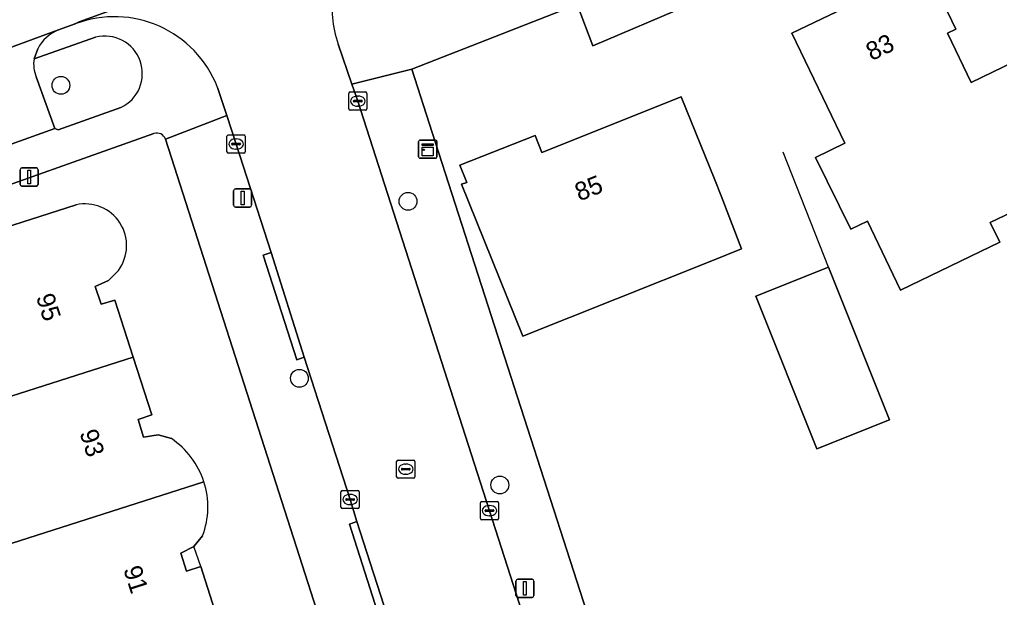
# Model space of a CAD drawing. Extents: x 159499 to 160349, y 382524 to 383273.
# Drawn here: x 159697.8 to 159751.6, y 382905.5 to 382937.3 of the extents above; entities that cross this region are included whole.
import ezdxf

# ---------------------------------------------------------------- set-up
doc = ezdxf.new("R2010")
doc.units = 0
for name, color, linetype in [('IMGEO_Boom', 7, 'Continuous'), ('IMGEO_Erf', 7, 'Continuous'), ('IMGEO_Groenvoorziening', 7, 'Continuous'), ('IMGEO_Kast', 7, 'Continuous'), ('IMGEO_Kolk', 7, 'Continuous'), ('IMGEO_Lichtmast', 7, 'Continuous'), ('IMGEO_Muur', 7, 'Continuous'), ('IMGEO_Pand', 7, 'Continuous'), ('IMGEO_Pand_nummerreeks', 7, 'Continuous'), ('IMGEO_Pand_overbouw', 7, 'Continuous'), ('IMGEO_Parkeervlak_open', 7, 'Continuous'), ('IMGEO_Rijbaan_lokaal_open', 7, 'Continuous'), ('IMGEO_Rioolput', 7, 'Continuous'), ('IMGEO_Voetpad_open', 7, 'Continuous')]:
    doc.layers.add(name, color=color, linetype=linetype)

msp = doc.modelspace()

# ---------------------------------------------------------------- linework, layer by layer
at = {"layer": 'IMGEO_Boom'}
for centre in [(159700.08, 382933.657), (159719.132, 382927.291), (159713.169, 382917.577), (159724.168, 382911.72)]:
    msp.add_circle(centre, 0.489, dxfattribs=at)
at = {"layer": 'IMGEO_Erf'}
for points in [[(159797.571, 382912.547), (159772.924, 382944.336), (159765.561, 382953.83), (159760.969, 382951.204), (159750.017, 382945.267), (159739.773, 382940.307), (159729.278, 382935.832), (159728.417, 382938.099), (159719.333, 382934.542), (159720.458, 382931.079), (159730.546, 382899.75), (159741.202, 382899.547), (159744.626, 382889.831), (159753.21, 382866.555), (159754.229, 382863.79), (159753.482, 382863.418), (159757.881, 382849.879), (159758.599, 382850.174), (159770.661, 382815.939), (159788.308, 382822.433), (159800.223, 382826.817), (159778.58, 382886.258)], [(159705.183, 382931.016), (159693.83, 382926.996), (159694.458, 382925.034), (159700.907, 382927.1)], [(159726.407, 382866.582), (159705.82, 382930.705)], [(159703.231, 382923.497), (159702.683, 382922.941), (159701.96, 382922.621), (159702.281, 382921.646), (159703.039, 382921.871), (159704.053, 382918.73), (159705.074, 382915.569), (159704.312, 382915.321), (159704.61, 382914.342), (159705.416, 382914.469), (159706.142, 382914.264)], [(159707.857, 382908.933), (159707.38, 382908.35), (159706.66, 382907.98), (159706.973, 382906.993), (159707.752, 382907.236), (159708.761, 382904.08), (159709.772, 382900.92), (159709.011, 382900.677), (159709.32, 382899.685), (159710.133, 382899.802), (159710.86, 382899.584)]]:
    msp.add_lwpolyline(points, dxfattribs=at)
for points in [[(159751.087, 382926.132), (159751.61, 382925.043), (159746.157, 382922.42), (159744.341, 382926.195), (159743.443, 382925.765), (159741.493, 382929.697), (159743.097, 382930.481), (159740.204, 382936.523), (159747.59, 382940.076), (159748.977, 382937.192), (159749.194, 382936.741), (159748.744, 382936.525), (159750.044, 382933.821), (159753.561, 382935.525), (159755.739, 382931.025), (159756.785, 382928.864)], [(159725.438, 382919.888), (159722.063, 382928.238), (159722.355, 382928.325), (159721.967, 382929.268), (159726.113, 382930.902), (159726.478, 382929.977), (159734.124, 382933.034), (159735.964, 382928.466), (159736.312, 382927.602), (159737.426, 382924.677), (159735.712, 382923.992)], [(159741.573, 382913.703), (159738.223, 382922.088), (159742.216, 382923.683), (159745.566, 382915.298)]]:
    msp.add_lwpolyline(points, close=True, dxfattribs=at)
for centre, radius, start, end in [((159705.343, 382930.537), 0.505, 19.442, 108.5123), ((159701.397, 382924.865), 2.288, 323.277, 102.3685), ((159703.632, 382910.513), 4.513, 17.8179, 56.2153), ((159703.634, 382910.517), 4.51, 339.437, 17.7771)]:
    msp.add_arc(centre, radius, start, end, dxfattribs=at)
at = {"layer": 'IMGEO_Groenvoorziening'}
for points in [[(159701.984, 382936.301), (159698.608, 382935.111)], [(159698.723, 382934.125), (159699.744, 382931.29), (159699.937, 382931.216), (159703.363, 382932.44)]]:
    msp.add_lwpolyline(points, dxfattribs=at)
for centre, radius, start, end in [((159702.488, 382934.304), 2.059, 295.1539, 104.1556), ((159700.307, 382934.809), 1.725, 169.9327, 203.3724)]:
    msp.add_arc(centre, radius, start, end, dxfattribs=at)
at = {"layer": 'IMGEO_Kast'}
for p, q in [((159719.714, 382929.731), (159719.714, 382930.572)), ((159719.714, 382930.572), (159719.714, 382929.731)), ((159719.789, 382930.656), (159720.63, 382930.656)), ((159720.63, 382930.656), (159719.789, 382930.656)), ((159720.714, 382930.581), (159720.714, 382929.74)), ((159720.714, 382929.74), (159720.714, 382930.581)), ((159720.639, 382929.656), (159719.798, 382929.656)), ((159719.798, 382929.656), (159720.639, 382929.656))]:
    msp.add_line(p, q, dxfattribs=at)
for points in [[(159719.909, 382930.446), (159720.509, 382930.446), (159720.509, 382930.361), (159719.909, 382930.361), (159719.909, 382930.446)], [(159719.909, 382930.271), (159720.509, 382930.271), (159720.509, 382929.782), (159719.909, 382929.782), (159719.909, 382930.271)]]:
    msp.add_lwpolyline(points, dxfattribs=at)
msp.add_circle((159719.993, 382930.12), 0.0377, dxfattribs=at)
for centre, start, end in [((159719.792, 382930.578), 92.4484, 184.2845), ((159719.792, 382930.578), 92.4484, 184.2845), ((159720.636, 382930.578), 2.4484, 94.2845), ((159720.636, 382930.578), 2.4484, 94.2845), ((159719.792, 382929.734), 182.4484, 274.2845), ((159719.792, 382929.734), 182.4484, 274.2845), ((159720.636, 382929.734), 272.4484, 4.2845), ((159720.636, 382929.734), 272.4484, 4.2845)]:
    msp.add_arc(centre, 0.0779, start, end, dxfattribs=at)
at = {"layer": 'IMGEO_Kolk'}
for p, q in [((159715.877, 382932.368), (159715.877, 382933.22)), ((159715.952, 382933.294), (159716.804, 382933.294)), ((159716.878, 382933.22), (159716.878, 382932.368)), ((159716.136, 382932.788), (159716.136, 382932.8)), ((159716.574, 382932.751), (159716.176, 382932.751)), ((159716.179, 382932.837), (159716.577, 382932.837)), ((159716.365, 382933.074), (159716.39, 382933.074)), ((159716.62, 382932.8), (159716.62, 382932.788)), ((159716.804, 382932.294), (159715.952, 382932.294)), ((159716.388, 382932.514), (159716.363, 382932.514)), ((159709.192, 382930.01), (159709.192, 382930.862)), ((159709.267, 382930.936), (159710.119, 382930.936)), ((159709.68, 382930.716), (159709.705, 382930.716)), ((159710.193, 382930.862), (159710.193, 382930.01)), ((159709.451, 382930.43), (159709.451, 382930.442)), ((159709.889, 382930.393), (159709.491, 382930.393)), ((159709.494, 382930.479), (159709.892, 382930.479)), ((159709.703, 382930.156), (159709.678, 382930.156)), ((159709.935, 382930.442), (159709.935, 382930.43)), ((159710.119, 382929.936), (159709.267, 382929.936)), ((159715.45, 382910.499), (159715.45, 382911.351)), ((159715.525, 382911.425), (159716.377, 382911.425)), ((159715.938, 382911.205), (159715.963, 382911.205)), ((159716.451, 382911.351), (159716.451, 382910.499)), ((159715.709, 382910.919), (159715.709, 382910.931)), ((159716.147, 382910.882), (159715.749, 382910.882)), ((159715.752, 382910.968), (159716.15, 382910.968)), ((159715.961, 382910.645), (159715.936, 382910.645)), ((159716.193, 382910.931), (159716.193, 382910.919)), ((159723.1, 382909.885), (159723.1, 382910.737)), ((159723.175, 382910.811), (159724.027, 382910.811)), ((159724.101, 382910.737), (159724.101, 382909.885)), ((159716.377, 382910.425), (159715.525, 382910.425)), ((159723.359, 382910.305), (159723.359, 382910.317)), ((159723.797, 382910.268), (159723.399, 382910.268)), ((159723.402, 382910.354), (159723.8, 382910.354)), ((159723.588, 382910.591), (159723.613, 382910.591)), ((159723.843, 382910.317), (159723.843, 382910.305)), ((159724.027, 382909.811), (159723.175, 382909.811)), ((159723.611, 382910.031), (159723.586, 382910.031))]:
    msp.add_line(p, q, dxfattribs=at)
for points in [[(159715.877, 382932.368), (159715.877, 382933.22)], [(159715.952, 382933.294), (159716.804, 382933.294)], [(159716.878, 382933.22), (159716.878, 382932.368)], [(159716.804, 382932.294), (159715.952, 382932.294)], [(159709.192, 382930.01), (159709.192, 382930.862)], [(159709.267, 382930.936), (159710.119, 382930.936)], [(159710.193, 382930.862), (159710.193, 382930.01)], [(159710.119, 382929.936), (159709.267, 382929.936)], [(159715.45, 382910.499), (159715.45, 382911.351)], [(159715.525, 382911.425), (159716.377, 382911.425)], [(159716.451, 382911.351), (159716.451, 382910.499)], [(159723.1, 382909.885), (159723.1, 382910.737)], [(159723.175, 382910.811), (159724.027, 382910.811)], [(159724.101, 382910.737), (159724.101, 382909.885)], [(159716.377, 382910.425), (159715.525, 382910.425)], [(159724.027, 382909.811), (159723.175, 382909.811)]]:
    msp.add_lwpolyline(points, dxfattribs=at)
for centre, radius, start, end in [((159715.954, 382933.218), 0.0765, 91.552, 178.448), ((159715.954, 382933.218), 0.0765, 91.552, 178.448), ((159716.802, 382933.218), 0.0765, 1.552, 88.448), ((159716.802, 382933.218), 0.0765, 1.552, 88.448), ((159716.176, 382932.797), 0.0403, 85.8775, 175.7526), ((159716.173, 382932.787), 0.0366, 178.938, 274.7102), ((159716.577, 382932.794), 0.043, 264.8664, 352.4533), ((159716.581, 382932.799), 0.0386, 1.7309, 96.639), ((159715.954, 382932.37), 0.0765, 181.552, 268.448), ((159715.954, 382932.37), 0.0765, 181.552, 268.448), ((159716.802, 382932.37), 0.0765, 271.552, 358.448), ((159716.802, 382932.37), 0.0765, 271.552, 358.448), ((159709.269, 382930.86), 0.0765, 91.552, 178.448), ((159709.269, 382930.86), 0.0765, 91.552, 178.448), ((159710.117, 382930.86), 0.0765, 1.552, 88.448), ((159710.117, 382930.86), 0.0765, 1.552, 88.448), ((159709.269, 382930.012), 0.0765, 181.552, 268.448), ((159709.269, 382930.012), 0.0765, 181.552, 268.448), ((159709.491, 382930.439), 0.0403, 85.8775, 175.7526), ((159709.488, 382930.429), 0.0366, 178.938, 274.7102), ((159709.892, 382930.436), 0.043, 264.8664, 352.4533), ((159709.896, 382930.441), 0.0386, 1.7309, 96.639), ((159710.117, 382930.012), 0.0765, 271.552, 358.448), ((159710.117, 382930.012), 0.0765, 271.552, 358.448), ((159715.527, 382911.349), 0.0765, 91.552, 178.448), ((159715.527, 382911.349), 0.0765, 91.552, 178.448), ((159716.375, 382911.349), 0.0765, 1.552, 88.448), ((159716.375, 382911.349), 0.0765, 1.552, 88.448), ((159715.749, 382910.928), 0.0403, 85.8775, 175.7526), ((159715.746, 382910.918), 0.0366, 178.938, 274.7102), ((159716.15, 382910.925), 0.043, 264.8664, 352.4533), ((159716.154, 382910.93), 0.0386, 1.7309, 96.639), ((159723.177, 382910.735), 0.0765, 91.552, 178.448), ((159723.177, 382910.735), 0.0765, 91.552, 178.448), ((159724.025, 382910.735), 0.0765, 1.552, 88.448), ((159724.025, 382910.735), 0.0765, 1.552, 88.448), ((159715.527, 382910.501), 0.0765, 181.552, 268.448), ((159715.527, 382910.501), 0.0765, 181.552, 268.448), ((159716.375, 382910.501), 0.0765, 271.552, 358.448), ((159716.375, 382910.501), 0.0765, 271.552, 358.448), ((159723.399, 382910.314), 0.0403, 85.8775, 175.7526), ((159723.396, 382910.304), 0.0366, 178.938, 274.7102), ((159723.8, 382910.311), 0.043, 264.8664, 352.4533), ((159723.804, 382910.316), 0.0386, 1.7309, 96.639), ((159723.177, 382909.887), 0.0765, 181.552, 268.448), ((159723.177, 382909.887), 0.0765, 181.552, 268.448), ((159724.025, 382909.887), 0.0765, 271.552, 358.448), ((159724.025, 382909.887), 0.0765, 271.552, 358.448)]:
    msp.add_arc(centre, radius, start, end, dxfattribs=at)
for centre, major_axis, ratio, start_param, end_param in [((159716.364, 382932.794), (-0.387, 0.002), 0.722429, 4.712389, 7.853982), ((159716.389, 382932.794), (-0.39, 0.002), 0.717154, 1.570796, 4.712389), ((159709.679, 382930.436), (-0.387, 0.002), 0.722429, 4.712389, 7.853982), ((159709.704, 382930.436), (-0.39, 0.002), 0.717154, 1.570796, 4.712389), ((159715.937, 382910.925), (-0.387, 0.002), 0.722429, 4.712389, 7.853982), ((159715.962, 382910.925), (-0.39, 0.002), 0.717154, 1.570796, 4.712389), ((159723.587, 382910.311), (-0.387, 0.002), 0.722429, 4.712389, 7.853982), ((159723.612, 382910.311), (-0.39, 0.002), 0.717154, 1.570796, 4.712389)]:
    msp.add_ellipse(centre, major_axis=major_axis, ratio=ratio, start_param=start_param, end_param=end_param, dxfattribs=at)
at = {"layer": 'IMGEO_Lichtmast'}
for p, q in [((159697.84, 382928.224), (159697.84, 382929.024)), ((159697.84, 382929.024), (159697.84, 382928.224)), ((159697.94, 382929.124), (159698.73, 382929.124)), ((159698.73, 382929.124), (159697.94, 382929.124)), ((159698.83, 382929.024), (159698.83, 382928.224)), ((159698.83, 382928.224), (159698.83, 382929.024)), ((159698.73, 382928.124), (159697.94, 382928.124)), ((159697.94, 382928.124), (159698.73, 382928.124)), ((159709.558, 382927.075), (159709.558, 382927.875)), ((159709.558, 382927.875), (159709.558, 382927.075)), ((159709.658, 382927.975), (159710.448, 382927.975)), ((159710.448, 382927.975), (159709.658, 382927.975)), ((159710.548, 382927.875), (159710.548, 382927.075)), ((159710.548, 382927.075), (159710.548, 382927.875)), ((159710.448, 382926.975), (159709.658, 382926.975)), ((159709.658, 382926.975), (159710.448, 382926.975)), ((159725.049, 382905.647), (159725.049, 382906.447)), ((159725.049, 382906.447), (159725.049, 382905.647)), ((159725.149, 382906.547), (159725.939, 382906.547)), ((159725.939, 382906.547), (159725.149, 382906.547)), ((159726.039, 382906.447), (159726.039, 382905.647)), ((159726.039, 382905.647), (159726.039, 382906.447)), ((159725.939, 382905.547), (159725.149, 382905.547)), ((159725.149, 382905.547), (159725.939, 382905.547))]:
    msp.add_line(p, q, dxfattribs=at)
for points in [[(159698.26, 382928.999), (159698.41, 382928.999), (159698.41, 382928.249), (159698.26, 382928.249), (159698.26, 382928.999)], [(159709.978, 382927.85), (159710.128, 382927.85), (159710.128, 382927.1), (159709.978, 382927.1), (159709.978, 382927.85)], [(159725.469, 382906.422), (159725.619, 382906.422), (159725.619, 382905.672), (159725.469, 382905.672), (159725.469, 382906.422)]]:
    msp.add_lwpolyline(points, dxfattribs=at)
for centre, start, end in [((159697.94, 382929.024), 90, 180), ((159697.94, 382929.024), 90, 180), ((159698.73, 382929.024), 0, 90), ((159698.73, 382929.024), 360, 90), ((159697.94, 382928.224), 180, 270), ((159697.94, 382928.224), 180, 270), ((159698.73, 382928.224), 270, 0), ((159698.73, 382928.224), 270, 0), ((159709.658, 382927.875), 90, 180), ((159709.658, 382927.875), 90, 180), ((159710.448, 382927.875), 0, 90), ((159710.448, 382927.875), 360, 90), ((159709.658, 382927.075), 180, 270), ((159709.658, 382927.075), 180, 270), ((159710.448, 382927.075), 270, 0), ((159710.448, 382927.075), 270, 0), ((159725.149, 382906.447), 90, 180), ((159725.149, 382906.447), 90, 180), ((159725.939, 382906.447), 0, 90), ((159725.939, 382906.447), 360, 90), ((159725.149, 382905.647), 180, 270), ((159725.149, 382905.647), 180, 270), ((159725.939, 382905.647), 270, 0), ((159725.939, 382905.647), 270, 0)]:
    msp.add_arc(centre, 0.1, start, end, dxfattribs=at)
at = {"layer": 'IMGEO_Muur'}
msp.add_lwpolyline([(159742.216, 382923.683), (159739.725, 382929.983)], dxfattribs=at)
at = {"layer": 'IMGEO_Pand'}
for points in [[(159753.561, 382935.525), (159750.044, 382933.821), (159748.744, 382936.525), (159749.194, 382936.741), (159748.977, 382937.192), (159747.59, 382940.076), (159740.204, 382936.523), (159743.097, 382930.481), (159741.493, 382929.697), (159743.443, 382925.765), (159744.341, 382926.195), (159746.157, 382922.42), (159751.61, 382925.043), (159751.087, 382926.132), (159756.785, 382928.864), (159755.739, 382931.025)], [(159737.426, 382924.677), (159736.312, 382927.602), (159735.964, 382928.466), (159734.124, 382933.034), (159726.478, 382929.977), (159726.113, 382930.902), (159721.967, 382929.268), (159722.355, 382928.325), (159722.063, 382928.238), (159725.438, 382919.888), (159735.712, 382923.992)], [(159741.573, 382913.703), (159745.566, 382915.298), (159742.216, 382923.683), (159738.223, 382922.088)]]:
    msp.add_lwpolyline(points, close=True, dxfattribs=at)
for points in [[(159700.907, 382927.1), (159694.458, 382925.034), (159693.83, 382926.996), (159689.861, 382925.725), (159690.817, 382922.747), (159690.915, 382919.634), (159690.691, 382919.636), (159690.729, 382918.547), (159690.949, 382918.555), (159691.092, 382914.595), (159704.053, 382918.73), (159703.039, 382921.871), (159702.281, 382921.646), (159701.96, 382922.621), (159702.683, 382922.941), (159703.231, 382923.497)], [(159706.142, 382914.264), (159705.416, 382914.469), (159704.61, 382914.342), (159704.312, 382915.321), (159705.074, 382915.569), (159704.053, 382918.73), (159691.092, 382914.595), (159693.293, 382911.268), (159693.109, 382911.146), (159693.704, 382910.247), (159693.888, 382910.368), (159695.502, 382907.919), (159707.929, 382911.894)], [(159707.929, 382911.894), (159695.502, 382907.919), (159695.61, 382904.992), (159695.397, 382904.99), (159695.441, 382903.898), (159695.66, 382903.906), (159695.816, 382899.951), (159708.761, 382904.08), (159707.752, 382907.236), (159706.973, 382906.993), (159706.66, 382907.98), (159707.38, 382908.35), (159707.857, 382908.933)]]:
    msp.add_lwpolyline(points, dxfattribs=at)
for centre, radius, start, end in [((159701.397, 382924.865), 2.288, 323.277, 102.3685), ((159703.632, 382910.513), 4.513, 17.8179, 56.2153), ((159703.634, 382910.517), 4.51, 339.437, 17.7771)]:
    msp.add_arc(centre, radius, start, end, dxfattribs=at)
at = {"layer": 'IMGEO_Pand_overbouw'}
msp.add_lwpolyline([(159706.66, 382907.98), (159706.973, 382906.993), (159707.752, 382907.236), (159707.38, 382908.35)], close=True, dxfattribs=at)
at = {"layer": 'IMGEO_Parkeervlak_open'}
for points in [[(159699.946, 382936.7), (159696.099, 382935.301), (159684.439, 382931.051), (159670.727, 382926.129)], [(159698.608, 382935.111), (159698.811, 382935.67)], [(159686.72, 382930.428), (159687.941, 382927.056), (159699.744, 382931.29), (159698.723, 382934.125)]]:
    msp.add_lwpolyline(points, dxfattribs=at)
for centre, radius, start, end in [((159700.765, 382934.657), 2.201, 111.851, 152.5958), ((159700.307, 382934.809), 1.725, 169.9327, 203.3724)]:
    msp.add_arc(centre, radius, start, end, dxfattribs=at)
at = {"layer": 'IMGEO_Rijbaan_lokaal_open'}
for points in [[(159696.099, 382935.301), (159699.946, 382936.7), (159700.852, 382937.031), (159701.086, 382937.144), (159718.304, 382943.378), (159720.187, 382944.082), (159733.185, 382949.569), (159742.119, 382953.821), (159754.023, 382960.12), (159754.237, 382960.246), (159754.457, 382960.36), (159758.932, 382962.886), (159764.112, 382965.984), (159768.323, 382968.671), (159768.781, 382968.963), (159771.016, 382970.427), (159767.275, 382976.094), (159764.296, 382974.173)], [(159729.441, 382940.798), (159727.639, 382940.031), (159728.417, 382938.099), (159729.278, 382935.832), (159739.773, 382940.307), (159750.017, 382945.267), (159760.969, 382951.204)], [(159718.304, 382943.378), (159701.086, 382937.144), (159700.852, 382937.031)], [(159716.376, 382932.797), (159716.054, 382933.725), (159715.295, 382935.916)], [(159708.676, 382933.54), (159709.177, 382932.011), (159709.693, 382930.436), (159711.615, 382924.477), (159713.429, 382918.737), (159715.951, 382910.926), (159716.328, 382909.718), (159718.16, 382903.979), (159718.821, 382901.909), (159725.562, 382904.205), (159716.376, 382932.797)]]:
    msp.add_lwpolyline(points, dxfattribs=at)
for centre, radius, start, end in [((159721.089, 382937.917), 6.13, 117.0216, 199.0556), ((159703.009, 382931.353), 6.074, 21.1052, 110.8028)]:
    msp.add_arc(centre, radius, start, end, dxfattribs=at)
at = {"layer": 'IMGEO_Rioolput'}
for p, q in [((159718.506, 382912.164), (159718.506, 382913.016)), ((159718.581, 382913.09), (159719.433, 382913.09)), ((159718.994, 382912.87), (159719.019, 382912.87)), ((159719.507, 382913.016), (159719.507, 382912.164)), ((159718.765, 382912.584), (159718.765, 382912.596)), ((159719.203, 382912.547), (159718.805, 382912.547)), ((159718.808, 382912.633), (159719.206, 382912.633)), ((159719.017, 382912.31), (159718.992, 382912.31)), ((159719.249, 382912.596), (159719.249, 382912.584)), ((159719.433, 382912.09), (159718.581, 382912.09))]:
    msp.add_line(p, q, dxfattribs=at)
for points in [[(159718.506, 382912.164), (159718.506, 382913.016)], [(159718.581, 382913.09), (159719.433, 382913.09)], [(159719.507, 382913.016), (159719.507, 382912.164)], [(159719.433, 382912.09), (159718.581, 382912.09)]]:
    msp.add_lwpolyline(points, dxfattribs=at)
for centre, radius, start, end in [((159718.583, 382913.014), 0.0765, 91.552, 178.448), ((159718.583, 382913.014), 0.0765, 91.552, 178.448), ((159719.431, 382913.014), 0.0765, 1.552, 88.448), ((159719.431, 382913.014), 0.0765, 1.552, 88.448), ((159718.805, 382912.593), 0.0403, 85.8775, 175.7526), ((159718.802, 382912.583), 0.0366, 178.938, 274.7102), ((159719.206, 382912.59), 0.043, 264.8664, 352.4533), ((159719.21, 382912.595), 0.0386, 1.7309, 96.639), ((159718.583, 382912.166), 0.0765, 181.552, 268.448), ((159718.583, 382912.166), 0.0765, 181.552, 268.448), ((159719.431, 382912.166), 0.0765, 271.552, 358.448), ((159719.431, 382912.166), 0.0765, 271.552, 358.448)]:
    msp.add_arc(centre, radius, start, end, dxfattribs=at)
for centre, major_axis, ratio, start_param, end_param in [((159718.993, 382912.59), (-0.387, 0.002), 0.722429, 4.712389, 7.853982), ((159719.018, 382912.59), (-0.39, 0.002), 0.717154, 1.570796, 4.712389)]:
    msp.add_ellipse(centre, major_axis=major_axis, ratio=ratio, start_param=start_param, end_param=end_param, dxfattribs=at)
at = {"layer": 'IMGEO_Voetpad_open'}
for points in [[(159715.295, 382935.916), (159716.054, 382933.725), (159719.333, 382934.542), (159728.417, 382938.099), (159727.639, 382940.031), (159722.099, 382937.803)], [(159700.852, 382937.031), (159699.946, 382936.7)], [(159698.811, 382935.67), (159698.608, 382935.111), (159701.984, 382936.301)], [(159732.164, 382894.706), (159731.353, 382897.234), (159730.546, 382899.75), (159720.458, 382931.079), (159719.333, 382934.542), (159716.054, 382933.725), (159716.376, 382932.797), (159725.562, 382904.205), (159725.632, 382903.985), (159726.994, 382899.746), (159727.07, 382899.511), (159737.539, 382866.925), (159744.191, 382846.188), (159744.243, 382846.026), (159745.318, 382842.675), (159745.694, 382841.502), (159751.166, 382824.443), (159759.246, 382799.219), (159765.262, 382780.583)], [(159705.82, 382930.705), (159709.177, 382932.011), (159708.676, 382933.54)], [(159703.363, 382932.44), (159699.937, 382931.216), (159699.744, 382931.29), (159687.941, 382927.056), (159687.842, 382926.87), (159686.27, 382926.274), (159686.072, 382926.349), (159674.286, 382922.088), (159674.183, 382921.921), (159673.23, 382921.572)], [(159717.74, 382903.838), (159715.911, 382909.577), (159716.328, 382909.718), (159715.951, 382910.926), (159713.429, 382918.737), (159713.024, 382918.592), (159711.188, 382924.338), (159711.615, 382924.477), (159709.693, 382930.436), (159709.177, 382932.011), (159705.82, 382930.705), (159726.407, 382866.582)], [(159681.49, 382922.46), (159689.861, 382925.725), (159693.83, 382926.996), (159705.183, 382931.016)]]:
    msp.add_lwpolyline(points, dxfattribs=at)
for points in [[(159711.615, 382924.477), (159711.188, 382924.338), (159713.024, 382918.592), (159713.429, 382918.737)], [(159716.328, 382909.718), (159715.911, 382909.577), (159717.74, 382903.838), (159718.16, 382903.979)]]:
    msp.add_lwpolyline(points, close=True, dxfattribs=at)
for centre, radius, start, end in [((159721.089, 382937.917), 6.13, 117.0216, 199.0556), ((159703.009, 382931.353), 6.074, 21.1052, 110.8028), ((159700.765, 382934.657), 2.201, 111.851, 152.5958), ((159702.488, 382934.304), 2.059, 295.1539, 104.1556), ((159705.343, 382930.537), 0.505, 19.442, 108.5123)]:
    msp.add_arc(centre, radius, start, end, dxfattribs=at)

# ---------------------------------------------------------------- texts
at = {"layer": 'IMGEO_Pand_nummerreeks'}
for s, rotation, p in [('83', 25.6914, (159744.574, 382934.985)), ('85', 21.685, (159728.537, 382927.283)), ('95', 287.7795, (159698.702, 382922.046)), ('93', 287.7795, (159701.093, 382914.59)), ('91', 287.7795, (159703.495, 382907.1))]:
    msp.add_text(s, height=1, rotation=rotation, dxfattribs=at).set_placement(p)

doc.saveas('drawing.dxf')
